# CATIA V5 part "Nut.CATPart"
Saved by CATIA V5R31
Part number: nut
Bounding box of the stored display mesh (mm): x -13.856 to 13.856, y 0 to 9, z -12 to 12
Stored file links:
  D:\PROJECTS\Project 2021\US EDITION\CATIA V5 6R 2021\Resources\Part Files\c14_catia_v5_6r2021_prt\c14-catia-v5-6r2021-figr-14-26 & 27\Part & Asm\Nut.CATPart
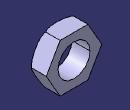
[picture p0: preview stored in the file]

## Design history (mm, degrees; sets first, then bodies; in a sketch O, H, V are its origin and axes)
Body1 (main body)
  Sketch1 on zx-plane, origin (0, 0, 0), H (-1, 0, 0), V (0, 0, 1)
    circle A1 centre (0, 0) radius 8
    construction circle A2 centre (0, 0) radius 12
    point P1 (-6.9282, -12)
    point P2 (6.9282, -12)
    point P3 (13.8564, 0)
    point P4 (6.9282, 12)
    point P5 (-6.9282, 12)
    point P6 (-13.8564, 0)
    point P7 (0, -12)
    line L1 (-6.9282, -12) -> (6.9282, -12)
    line L2 (6.9282, -12) -> (13.8564, 0)
    line L3 (13.8564, 0) -> (6.9282, 12)
    line L4 (6.9282, 12) -> (-6.9282, 12)
    line L5 (-6.9282, 12) -> (-13.8564, 0)
    line L6 (-13.8564, 0) -> (-6.9282, -12)
    construction line L7 (0, 0) -> (0, -12)
    construction circle A3 centre (0, 0) radius 13.8564
    construction arc A4 centre (-6.9282, 12) radius 13.8564 from (6.9282, 12) to (-13.8564, 0) cw
    construction arc A5 centre (6.9282, -12) radius 13.8564 from (13.8564, 0) to (-6.9282, -12) ccw
    radius A1 = 8
    radius A2 = 12
    coincidence: P7 A2, A3 P1, A3 P2, A3 P3, A3 P4, A3 P5, A3 P6, A4 O, A5 O
    vertical: L7 V
    midpoint: P7 L1
    parallelism: L1 L4
  Pad1: profile Sketch1, direction (0, 1, 0), length 9
  Sketch2 on xy-plane, origin (0, 0, 0), H (1, 0, 0), V (0, 1, 0)
    projected line E1 (10.7061, 0) -> (13.8564, 0) from edge of Pad1
    point P1 (13.8564, 0)
    projected line E2 (13.8564, 0) -> (13.8564, 1.8188) from edge of Pad1
    point P2 (13.8564, 0)
    arc A1 centre (10.7061, 3.6376) radius 3.6376 from (10.7061, 0) to (13.8564, 1.8188) ccw
    coincidence: P1 P2
    tangency: A1 E1
  Groove1: profile Sketch2, axis axis of face of Pad1, angle 360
